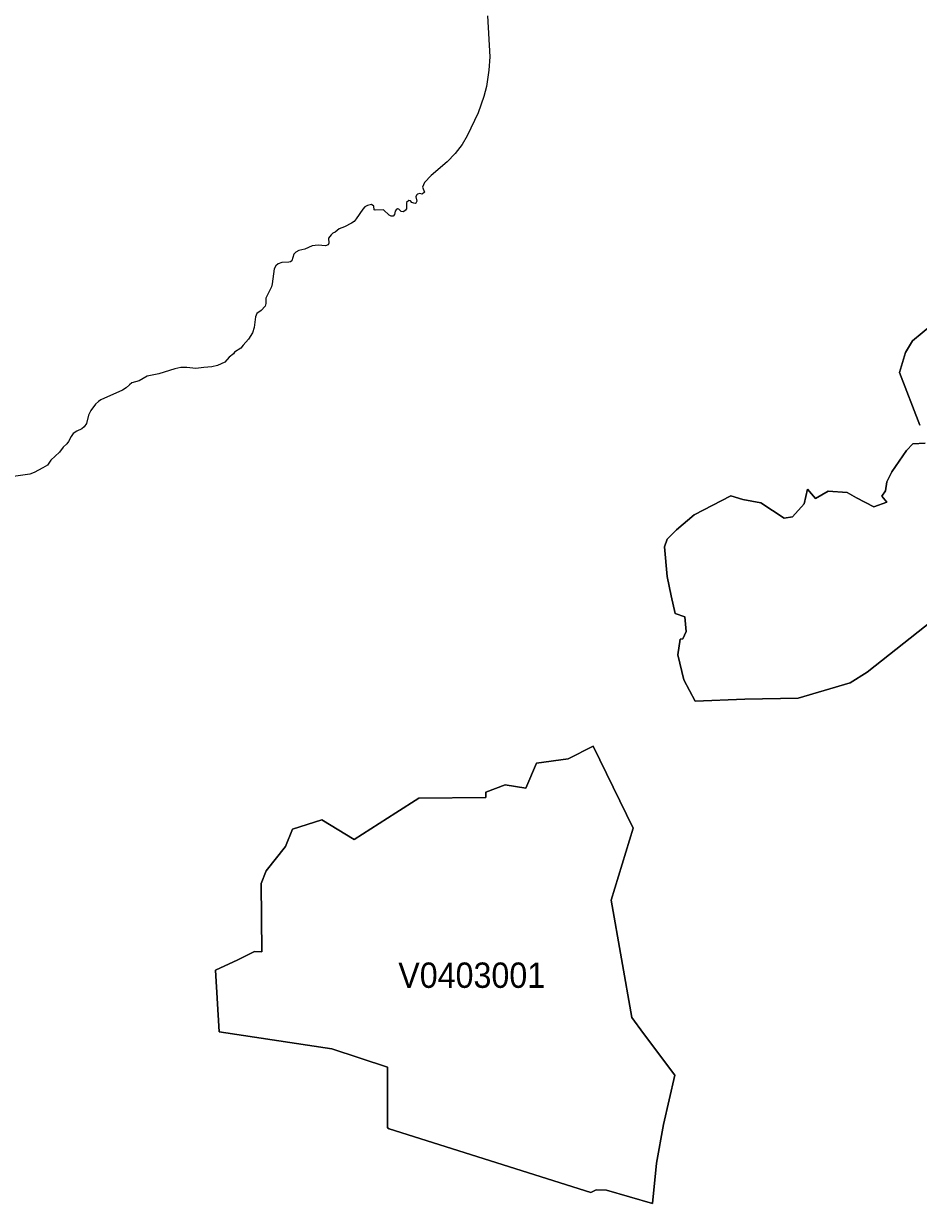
# Model space of a CAD drawing. Extents: x 369010 to 735936, y 6377141 to 6616555.
# Drawn here: x 411133 to 414663, y 6491553 to 6496204 of the extents above; entities that cross this region are included whole.
import ezdxf
from ezdxf.enums import TextEntityAlignment as Align

# ---------------------------------------------------------------- set-up
doc = ezdxf.new("R2010")
doc.units = 0
doc.header["$LTSCALE"] = 40
doc.layers.add('3', color=7, linetype='Continuous', lineweight=13)
doc.layers.add('4', color=7, linetype='Continuous')

msp = doc.modelspace()

# ---------------------------------------------------------------- linework, layer by layer
at = {"layer": '3'}
for points in [[(412963.6, 6496234.85), (412972.21, 6496072.82), (412968.73, 6496021.02), (412958.63, 6495956.31), (412949.2, 6495917.41), (412926.2, 6495852.54), (412882.34, 6495761.84), (412862.64, 6495727.75)], [(412862.64, 6495727.75), (412835.5, 6495692.33), (412803.72, 6495659.39), (412741, 6495606.1), (412714.85, 6495577.47), (412706.9, 6495559.26), (412714.85, 6495539.4), (412705.91, 6495532.45), (412696.31, 6495534.44), (412686.55, 6495531.79), (412682.9, 6495528.65), (412680.59, 6495520.87), (412684.23, 6495504.98), (412680.92, 6495497.03), (412677.94, 6495495.38), (412672.31, 6495496.37), (412664.04, 6495499.02), (412658.91, 6495505.81), (412652.45, 6495507.63), (412644.18, 6495499.52), (412643.18, 6495474.03), (412639.54, 6495469.06), (412631.43, 6495462.61), (412622.5, 6495464.26), (412613.06, 6495473.37), (412608.1, 6495474.03), (412602.3, 6495470.39), (412598.99, 6495464.6), (412596.68, 6495452.18), (412591.55, 6495445.23), (412583.27, 6495444.9), (412575.16, 6495449.53), (412552.65, 6495470.39), (412519.39, 6495468.73), (412516.41, 6495470.72), (412514.75, 6495485.12), (412505.32, 6495490.74), (412489.6, 6495487.77), (412479.5, 6495481.81), (412470.73, 6495473.04), (412445.24, 6495434.14), (412436.63, 6495424.71), (412426.54, 6495417.26), (412399.07, 6495402.86), (412377.88, 6495395.58), (412362.16, 6495381.68), (412353.06, 6495378.37), (412345.94, 6495372.08), (412336.01, 6495359), (412336.67, 6495338.48), (412334.52, 6495332.85), (412323.93, 6495328.72), (412294.63, 6495330.7), (412271.13, 6495328.39), (412242.33, 6495314.65), (412218.83, 6495310.01), (412207.08, 6495303.89), (412198.97, 6495294.79), (412191.36, 6495269.63), (412185.57, 6495265.33), (412179.61, 6495263.34), (412152.46, 6495262.02), (412136.91, 6495256.89), (412127.97, 6495248.94), (412122.18, 6495237.19), (412113.57, 6495178.44), (412110.76, 6495166.69), (412088.75, 6495122.5), (412088.75, 6495100.98), (412085.93, 6495090.56), (412069.88, 6495073.51), (412052.83, 6495061.43), (412047.37, 6495047.86), (412042.4, 6495006.65), (412036.28, 6494984.8), (412020.56, 6494959.64), (411999.37, 6494936.64), (411990.77, 6494925.22), (411965.28, 6494908.67), (411961.64, 6494902.71), (411944.76, 6494888.97), (411926.55, 6494870.1), (411898.75, 6494856.37), (411875.25, 6494850.74), (411843.8, 6494848.92), (411813.18, 6494844.29), (411777.27, 6494848.26), (411753.77, 6494847.93), (411730.1, 6494843.29), (411667.37, 6494824.09), (411620.7, 6494814.83), (411588.76, 6494796.29), (411560.62, 6494787.52), (411550.53, 6494780.24), (411538.11, 6494768.49), (411523.71, 6494758.72), (411437.82, 6494721.15), (411428.38, 6494714.53), (411417.3, 6494703.44), (411398.59, 6494679.28)], [(414668.62, 6494621.02), (414588.35, 6494829.39), (414612.02, 6494908.01), (414639.16, 6494953.68), (414753.19, 6495047.86)], [(414753.19, 6495047.86), (414639.16, 6494953.68), (414612.02, 6494908.01), (414588.35, 6494829.39), (414668.62, 6494621.02)], [(411398.59, 6494679.28), (411389.49, 6494661.07), (411382.04, 6494627.97), (411372.11, 6494614.73), (411363.67, 6494607.12), (411342.82, 6494597.69), (411329.08, 6494587.92), (411320.31, 6494576.17), (411311.04, 6494557.14), (411303.59, 6494548.03), (411288.86, 6494534.96), (411275.13, 6494514.44), (411240.21, 6494482.66), (411227.79, 6494463.79), (411208.93, 6494452.37), (411174.83, 6494434.99), (411157.29, 6494428.21), (411074.87, 6494415.8)], [(413703.57, 6493879.23), (413688.01, 6493947.75), (413671.63, 6494024.05), (413661.2, 6494141.39), (413671.13, 6494172.01), (413708.2, 6494208.59), (413777.71, 6494267.67), (413923.19, 6494342.64), (413970.69, 6494327.58), (414041.2, 6494315.34), (414133.38, 6494254.43), (414166.65, 6494260.39), (414211.67, 6494310.54), (414225.4, 6494368.63), (414257.18, 6494332.38), (414306.83, 6494360.52), (414381.8, 6494355.88), (414418.38, 6494334.7), (414486.9, 6494299.45), (414538.54, 6494317.65), (414518.18, 6494341.15), (414533.24, 6494362.67), (414537.71, 6494398.42), (414557.24, 6494436.98), (414615.33, 6494521.22), (414640.82, 6494547.21), (414689.81, 6494550.85)], [(414689.81, 6494550.85), (414640.82, 6494547.21), (414615.33, 6494521.22), (414557.24, 6494436.98), (414537.71, 6494398.42), (414533.24, 6494362.67), (414518.18, 6494341.15), (414538.54, 6494317.65), (414486.9, 6494299.45), (414418.38, 6494334.7), (414381.8, 6494355.88), (414306.83, 6494360.52), (414257.18, 6494332.38), (414225.4, 6494368.63), (414211.67, 6494310.54), (414166.65, 6494260.39), (414133.38, 6494254.43), (414041.2, 6494315.34), (413970.69, 6494327.58), (413923.19, 6494342.64), (413777.71, 6494267.67), (413708.2, 6494208.59), (413671.13, 6494172.01), (413661.2, 6494141.39), (413671.63, 6494024.05), (413688.01, 6493947.75), (413703.57, 6493879.23), (413741.47, 6493866.16), (413747.1, 6493807.9), (413734.02, 6493779.1), (413723.59, 6493777.78), (413713.83, 6493715.22), (413737.99, 6493617.41), (413782.18, 6493532.83), (413978.3, 6493540.78), (414188, 6493545.41), (414394.05, 6493605.32), (414460.58, 6493647.2), (414775.37, 6493896.11)], [(414775.37, 6493896.11), (414460.58, 6493647.2), (414394.05, 6493605.32), (414188, 6493545.41), (413978.3, 6493540.78), (413782.18, 6493532.83), (413737.99, 6493617.41), (413713.83, 6493715.22), (413723.59, 6493777.78), (413734.02, 6493779.1), (413747.1, 6493807.9), (413741.47, 6493866.16), (413703.57, 6493879.23)]]:
    msp.add_lwpolyline(points, dxfattribs=at)
for points in [[(412601.97, 6493092.26), (412691.68, 6493150.19), (412956.65, 6493153.83), (412955.99, 6493174.68), (413032.95, 6493203.48), (413114.04, 6493190.4), (413155.75, 6493289.05), (413281.7, 6493305.26), (413380.34, 6493356.24), (413537.9, 6493032.35), (413450.51, 6492748.18), (413532.44, 6492286.42), (413578.12, 6492222.54), (413702.08, 6492058.19), (413656.9, 6491863.56), (413629.42, 6491712.12), (413614.2, 6491552.91), (413432.97, 6491605.37), (413391.76, 6491606.04), (413370.24, 6491595.61), (412574.83, 6491847.01), (412568.38, 6491850.98), (412568.87, 6492090.13), (412348.75, 6492162.13), (411904.71, 6492228.99), (411889.81, 6492472.45), (411978.85, 6492513.66), (412044.56, 6492546.26), (412073.35, 6492544.44), (412069.88, 6492814.38), (412090.24, 6492864.69), (412166.7, 6492959.53), (412193.34, 6493028.87), (412309.03, 6493065.78), (412437.46, 6492987.17)], [(412601.97, 6493092.26), (412437.46, 6492987.17), (412309.03, 6493065.78), (412193.34, 6493028.87), (412166.7, 6492959.53), (412090.24, 6492864.69), (412069.88, 6492814.38), (412073.35, 6492544.44), (412044.56, 6492546.26), (411978.85, 6492513.66), (411889.81, 6492472.45), (411904.71, 6492228.99), (412348.75, 6492162.13), (412568.87, 6492090.13), (412568.38, 6491850.98), (412574.83, 6491847.01), (413370.24, 6491595.61), (413391.76, 6491606.04), (413432.97, 6491605.37), (413614.2, 6491552.91), (413629.42, 6491712.12), (413656.9, 6491863.56), (413702.08, 6492058.19), (413578.12, 6492222.54), (413532.44, 6492286.42), (413450.51, 6492748.18), (413537.9, 6493032.35), (413380.34, 6493356.24), (413281.7, 6493305.26), (413155.75, 6493289.05), (413114.04, 6493190.4), (413032.95, 6493203.48), (412955.99, 6493174.68), (412956.65, 6493153.83), (412691.68, 6493150.19)]]:
    msp.add_lwpolyline(points, close=True, dxfattribs=at)

# ---------------------------------------------------------------- texts
at = {"layer": '4', "width": 0.95}
msp.add_text('V0403001', height=100, dxfattribs=at).set_placement((412900.8, 6492402.68), align=Align.CENTER)

doc.saveas('drawing.dxf')
